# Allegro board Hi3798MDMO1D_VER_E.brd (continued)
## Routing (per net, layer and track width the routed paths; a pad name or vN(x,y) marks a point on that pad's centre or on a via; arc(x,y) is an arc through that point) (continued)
USB0_DM: length 50.8
  TOP w0.127: U1.A6 v2(53.92,47)
  TOP w0.152: v1(81.67,61.35) 81.83,61.51 82.16,61.51 C119.1 D6.1 83.9,61.69 85.3,61.69 86.13,60.87 J12.2
  BOTTOM w0.152: v1(81.67,61.35) 81.39,61.64 81.07,61.64 77.61,65.1 70.71,65.1 69.81,64.21 67.5,64.21 62.77,59.48 55.53,59.48 53.37,57.32 53.37,54.3 53.53,54.15 53.53,53.87 53.37,53.72 53.37,53.44 53.53,53.29 53.53,53.01 53.37,52.86 53.37,52.58 53.53,52.43 53.53,52.15 53.37,51.99 53.37,51.71 53.53,51.56 53.53,51.28 53.37,51.13 53.37,50.85 53.53,50.7 53.53,50.42 53.37,50.27 53.37,49.99 53.53,49.83 53.53,49.55 53.37,49.4 53.37,49.12 53.53,48.97 53.53,48.69 53.37,48.54 53.37,48.26 53.53,48.11 53.53,47.83 53.37,47.68 53.37,46.96 53.53,46.81 53.73,46.81 v2(53.92,47)
USB0_DP: length 50.9
  TOP w0.127: U1.B6 v2(53.92,46.2)
  TOP w0.152: J12.3 86.11,62.85 85.27,62.02 83.79,62.02 D1.1 C113.1 82.22,62.15 81.77,62.15 v1(81.67,62.25)
  BOTTOM w0.152: v2(53.92,46.2) 53.69,46.43 53.37,46.43 53.04,46.76 53.04,57.46 55.4,59.81 62.64,59.81 67.36,64.54 69.68,64.54 70.57,65.43 77.74,65.43 81.21,61.97 81.39,61.97 v1(81.67,62.25)
USB01_1V1: length 0.6
  TOP w0.305: U1.G11 57.52,41.8 v2(57.92,41.4)
USB01_3V3: length 0.6
  TOP w0.305: U1.D7 v2(54.72,44.6)
USB1_DM: length 76.4
  TOP w0.152: v1(36.89,61.77) 37.11,61.77 37.3,61.58 37.3,61.08 37.63,60.75 43.85,60.75 54.87,49.73 54.87,48.59 54.72,48.44 54.54,48.44 54.39,48.28 54.39,47.98 54.54,47.83 54.72,47.83 54.87,47.68 54.87,47.43 54.39,46.94 54.39,45.87 U1.B7 ; U7.7 22.59,30.96 22.26,31.29 20.86,31.29 20.68,31.47 20.68,32.29 20.78,32.39 21.03,32.39 v1(21.24,32.18)
  BOTTOM w0.152: v1(21.24,32.18) 20.1,32.18 19.59,32.69 19.59,33.83 19.08,34.35 J2.4 19.08,36.81 19.91,37.64 19.91,38.3 20.34,38.73 23.52,38.73 25.05,40.26 25.05,53.35 30,58.29 34.95,58.29 37.17,60.51 37.17,61.48 v1(36.89,61.77)
USB1_DP: length 76.4
  TOP w0.152: v1(37.78,61.77) 37.63,61.61 37.63,61.22 37.76,61.08 43.99,61.08 55.2,49.87 55.2,47.29 54.72,46.81 54.72,45.4 U1.C7 ; v1(21.24,32.94) 21.03,32.72 20.65,32.72 20.35,32.43 20.35,31.42 20.23,31.29 19.26,31.29 19.09,31.11 U7.6
  BOTTOM w0.152: v1(21.24,32.94) 20.81,32.51 20.24,32.51 19.92,32.82 19.92,33.52 21.08,34.68 J2.3 21.08,36.81 20.24,37.64 20.24,38.16 20.48,38.4 23.66,38.4 25.38,40.13 25.38,53.21 30.13,57.96 35.09,57.96 37.5,60.37 37.5,61.48 v1(37.78,61.77)
USB3_DM: length 46.2
  TOP w0.152: 63.12,29 63.12,29.12 63.01,29.22 62.75,29.22 62.65,29.12 62.65,28.13 62.8,27.98 63.05,27.98 63.2,27.82 63.2,27.52 63.05,27.37 62.8,27.37 62.65,27.21 62.65,26.91 62.8,26.76 63.05,26.76 63.2,26.6 63.2,26.3 63.05,26.15 62.8,26.15 62.65,25.99 62.65,25.32 65.44,22.53 75.89,22.53 77.26,21.16 77.26,20.07 79.24,18.08 79.24,13.17 83.09,9.32 85.35,9.32 86.41,10.37 86.41,14.04 86.07,14.38 85.59,14.38 85.35,14.13 J13.2
USB3_DP: length 46.1
  TOP w0.152: 63.12,29.8 62.88,29.55 62.62,29.55 62.31,29.25 62.31,25.18 65.3,22.2 75.76,22.2 76.93,21.02 76.93,19.93 78.91,17.95 78.91,13.03 82.96,8.99 85.49,8.99 86.74,10.24 86.74,14.18 86.21,14.71 85.91,14.71 J13.3
USB3_RXN: length 27.9
  TOP w0.152: U1.AB20 65.31,29.21 65.31,25.42 66.15,24.58 77.04,24.58 82.72,18.9 82.72,17.71 83.01,17.42 83.61,17.42 83.85,17.65 J13.5
USB3_RXP: length 27.9
  TOP w0.152: J13.6 83.85,16.86 83.61,17.09 82.87,17.09 82.39,17.57 82.39,18.76 76.9,24.25 66.01,24.25 64.98,25.28 64.98,26.4 64.88,26.51 64.75,26.51 64.6,26.66 64.6,26.96 64.75,27.12 64.88,27.12 64.98,27.22 64.98,28.74 U1.AC20
USB3_TXN: length 26.6
  TOP w0.152: C77.2 80.87,18.43 80.61,18.68 80.61,19.1 76.12,23.59 65.77,23.59 64.17,25.19 64.17,27.53 64.32,27.68 64.4,27.68 64.55,27.83 64.55,28.14 64.4,28.29 64.32,28.29 64.17,28.44 64.17,28.89 63.84,29.22 63.84,29.51 63.97,29.64 64.19,29.64 64.32,29.76 64.32,30.04 64.19,30.17 63.94,30.17 63.84,30.27 63.84,30.52 63.9,30.58 U1.AA19
USB3_TXP: length 26.2
  TOP w0.152: C81.2 80.28,18.63 80.28,18.96 75.98,23.26 65.63,23.26 63.84,25.06 63.84,28.75 63.51,29.08 63.51,30.99 U1.Y19
USB_BOOT: length 9.8
  BOTTOM w0.127: S2.1 78.44,45.18 ; 78.44,45.18 84.64,45.18 S2.2 ; 78.44,45.18 C109.1 R40.1
VDAC_3V3: length 2.6
  TOP w0.305: U1.G19 64,41.88 64,42.52 U1.F19 63.92,42.6 U1.E20 v2(65.12,43.8)
XIN: length 10.8
  TOP w0.203: X2.1 75.61,29.73 75.14,30.2 73.12,30.2 72.33,29.41 C364.1 72.18,29.51 R1.2 70.37,30.17 70.04,30.17 68.01,32.2 67.12,32.2
XOUT: length 7.4
  TOP w0.203: U1.W22 66.71,32.58 68.21,32.58 70.24,30.55 70.6,30.55 R1.1 71.71,30.3 R14.1
$4N774: length 3.5
  TOP w0.381: C43.1 R7.2 67.74,50.39 C71.1 67.34,49.99 67.34,49.53 R21.1
$4N775: length 7.1
  TOP w0.381: R70.1 69.43,53.92 R53.1 C76.1 72.58,53.92 R99.2 73.19,52.89 73.95,52.12 U11.6
$4N782: length 3.5
  TOP w0.381: v1(72.33,52.63) 72.33,52.6 U11.1
  BOTTOM w0.127: v1(72.33,52.63) 73.44,52.63 R73.2 74.01,52.48 74.26,52.73 C8.1
$4N811: length 5.3
  TOP w0.508: R13.2 72.27,11.98 72.27,11.42 71.69,10.84 R101.1 C82.1 ; R13.2 R110.1 ; R13.2 71.88,11.98 71.41,11.98 71.21,12.18 U13.6
$4N812: length 40.1
  TOP w0.127: v1(69.78,45.66) 69.52,45.4 C72.1 68.89,44.75 68.87,44.72 R23.1 ; R102.2 C45.1 72.27,15.53 73.17,16.43 73.17,20.33 v1(74.08,21.23)
  BOTTOM w0.127: v1(69.78,45.66) 70.72,45.66 75.09,41.3 75.09,38.83 78.01,35.91 78.01,25.17 v1(74.08,21.23)
$4N813: length 1
  TOP w0.381: R110.2 R102.1
$4N818: length 3.9
  TOP w0.381: v1(71.72,15.88) 71.7,15.9 71.24,15.9 70.83,15.49 U13.1
  BOTTOM w0.381: R81.2 C5.1 71.54,16.06 v1(71.72,15.88)
$4N881: length 5
  TOP w0.381: U15.5 15.11,40.52 14.77,40.18 R52.1 15.27,39.19 15.38,39.29 R10.1 C84.1
$4N883: length 3.3
  TOP w0.381: R35.2 20.07,38.35 C30.1 R6.2 19.11,39.8 18.94,39.97 U15.1
$4N953: length 3.5
  TOP w0.381: v1(64.5,59.2) 64.96,59.66 U14.5
  BOTTOM w0.381: R105.1 R100.1 64.84,59.53 v1(64.5,59.2)
$4N955: length 4.1
  TOP w0.381: D2.1 73.09,54.89 72.39,55.6 v1(72.39,55.85) U14.1
  BOTTOM w0.381: R95.1 72.54,55.7 v1(72.39,55.85)
$4N956: length 1
  BOTTOM w0.381: R104.1 C83.2
$4N957: length 3.4
  TOP w0.381: v1(64.48,58.17) 64.71,58.39 U14.6
  BOTTOM w0.381: v1(64.48,58.17) 64.86,58.54 C24.1 C83.1
$4N958: length 3.6
  TOP w0.381: v1(64.48,56.39) 64.48,56.9 64.71,57.12 U14.7
  BOTTOM w0.381: v1(64.48,56.39) 64.48,55.75 64.82,55.42 R4.2
$4N975: length 2.9
  TOP w0.381: v1(64.5,54.81) 64.5,55.13 65.22,55.85 U14.8
  BOTTOM w0.381: C44.1 64.91,54.4 v1(64.5,54.81)
$4N980: length 1
  BOTTOM w0.381: C65.1 R95.2
$4N983: length 0.7
  BOTTOM w0.381: C65.2 v1(72.49,58.29)
$4N998: length 1
  TOP w0.381: R70.2 R7.1
$5N541: length 3.7
  TOP w0.381: R144.2 R118.2 75.32,19.63 75.62,19.32 75.62,18.44 Q4.3
$5N549: length 2.1
  TOP w0.381: Q4.1 74.32,15.41 73.82,15.91 R98.2
$6N188: length 2.8
  TOP w0.203: R14.2 C365.1 72.6,32 73.26,31.35 X2.3
$6N1407: length 1.6
  TOP w0.305: U1.E6 53.52,43.4 v2(53.12,43.8)
  BOTTOM w0.381: v2(53.12,43.8) 53.12,43.99 52.76,44.34 R173.1
$6N2001: length 2.5
  TOP w0.127: U1.Y17 v2(62.72,31.8)
  BOTTOM w0.127: R61.2 63,30.49 63.13,30.62 63.13,31.39 63.03,31.49 v2(62.72,31.8)
$6N2177: length 3.1
  TOP w0.203: U1.L19 63.92,38.6 64.32,39 v2(65.12,39)
  BOTTOM w0.305: R85.1 65.62,39.49 v2(65.12,39) 65.52,38.6 R43.1
$6N2315: length 7.6
  TOP w0.127: 51.12,43.4 50.4,44.12 48.83,44.12 47.41,45.54 R5.2
$6N2388: length 2
  TOP w0.127: 67.12,37 68.46,37 68.67,37.21 R65.2
$7N1408: length 1.2
  TOP w0.305: U1.G17 v2(62.72,42.2)
  BOTTOM w0.305: v2(62.72,42.2) 62.59,42.32 C250.2
$7N1630: length 18.6
  TOP w0.127: U1.H21 65.52,40.78 65.92,40.38 65.92,39.84 66.26,39.5 67.66,39.5 69.06,38.1 78.85,38.1 79.26,38.5 v1(79.26,40.77)
  BOTTOM w0.127: R40.2 v1(79.26,40.77)
$7N1639: length 4.1
  TOP w0.305: 55.12,44.2 v2(55.52,44.6)
  BOTTOM w0.305: R87.2 R18.2 55.79,46.63 56.04,46.38 56.04,45.12 v2(55.52,44.6)
$7N1763: length 1.3
  TOP w0.305: U1.F20 v2(65.12,43)
  BOTTOM w0.305: R32.2 65.22,43.1 v2(65.12,43)
$8N1506: length 1.3
  TOP w0.127: U1.W16 v2(61.12,31.8)
  BOTTOM w0.305: v2(61.12,31.8) 61.07,31.85 R45.1
$8N1514: length 4.3
  TOP w0.114: U1.AA7 54.32,30.33 53.88,29.89 53.88,28.63 54.49,28.02 54.89,27.62 54.89,27.24 54.89,27.24 R36.2
$8N1515: length 3.7
  TOP w0.114: U1.AB7 54.15,29.63 54.15,28.74 55.15,27.73 55.15,27.28 55.48,26.94 R37.2
$9N2352: length 1.5
  TOP w0.305: U1.T19 v2(64.32,35)
  BOTTOM w0.381: v2(64.32,35) 64.78,34.54 C255.2
$11N1061: length 4
  TOP w0.127: R54.2 36.94,38.17 36.94,41.62 U3.H8
$11N1180: length 3.9
  TOP w0.127: U6.H8 36.97,27.01 R55.2
$12N1392: length 4.2
  TOP w0.127: R71.2 45.06,13.64 44.98,13.71 41.85,13.71 U21.H8
$12N1506: length 4.5
  TOP w0.127: U20.H8 56.97,13.74 58.61,13.74 59.75,14.88 R75.2
$13N604: length 2.9
  TOP w0.089: U22.K2 89.27,34.12 89.92,34.12
  TOP w0.127: v2(89.95,34.12) 89.92,34.12
  BOTTOM w0.203: 89.95,34.12 90.33,34.5 C124.1 ; 89.95,34.12 89.31,34.75 C123.1 ; 89.95,34.12 v2(89.95,34.12)
$13N728: length 1.9
  TOP w0.254: U19.39 87.51,25.65 87.64,25.53 R68.1
$13N778: length 2
  TOP w0.254: R80.2 87.01,25.4 U19.38
$14N447: length 2
  TOP w0.381: U10.3 82.39,71.5 R15.1
$14N448: length 2.8
  TOP w0.381: U10.4 83.88,70.38 R41.2
$14N488:
  vias: v1(89.88,74.42) v1(89.88,73.53) v1(90.77,74.42) v1(90.77,73.53)
$14N520: length 1.4
  TOP w0.381: U12.3 74.78,12.02 R16.1
$14N521: length 1.3
  TOP w0.381: R42.2 73.72,9.03 U12.4
$14N524:
  vias: v1(79.92,8.3) v1(79.92,7.03) v1(81.19,8.3) v1(81.19,7.03)
$14N708: length 9.3
  TOP w0.152: J13.9 83.85,10.74 83.61,10.97 83,10.97 81.5,12.47 81.5,14.86 80.41,15.95 80.41,16.84 80.08,17.17 C81.1
$14N709: length 9
  TOP w0.152: C77.1 81.01,17.12 80.74,16.85 80.74,16.09 81.83,15 81.83,12.61 83.14,11.3 83.74,11.3 83.85,11.41 J13.8
$15N781: length 19.1
  TOP w0.127: R76.2 26.57,52.76 24.29,55.04 21.45,55.04 v1(20.94,55.55)
  BOTTOM w0.127: v1(20.94,55.55) 20.43,56.05 17.89,56.05 17.49,56.46 17.49,59.48 Q5.1
$15N941: length 2.3
  TOP w0.127: v1(65.41,8.35) 65.41,8.3 65.39,8.33 Q2.1
  BOTTOM w0.127: R31.2 65.95,7.64 65.41,8.17 v1(65.41,8.35)
$15N943: length 2.9
  TOP w0.127: v1(69.28,10.16) 68.41,9.29 Q1.1
  BOTTOM w0.127: R22.2 68.91,10.54 v1(69.28,10.16)
$15N992: length 7.9
  TOP w0.254: LED1.3 67.67,4.34 67.39,4.62 Q1.3 67.39,9.24 R2.2
$15N993: length 10
  TOP w0.254: R34.2 64.23,9.7 63.46,8.93 Q2.3 63.46,5.05 62.59,4.19 LED1.1
$16N996: length 5.3
  TOP w0.356: U5.5 57.71,67.87 57.69,67.88 C363.1
  TOP w0.381: R229.1 R90.2 R66.1 57.08,68.65 56.99,68.56 C363.1
$16N997: length 2.1
  TOP w0.356: C33.2 57.57,66.74 58.04,67.22 U5.6
$16N998: length 2.7
  TOP w0.356: U5.7 v1(60.11,66.57)
  BOTTOM w0.381: v1(60.11,66.57) 60.19,66.49 C32.1
$16N999: length 2.4
  TOP w0.356: U5.8 v1(63.66,66.57)
  BOTTOM w0.381: v1(63.66,66.57) 63.58,66.49 C32.2
$16N1080: length 2
  TOP w0.381: R49.2 R57.1 R91.2
$16N1087: length 1.3
  TOP w0.381: C351.2 58.77,59.42 R193.1
$16N1088: length 8.9
  TOP w0.254: U5.2 60.33,69.82 61.38,68.77 61.38,66.01 C55.1 59.88,64 59.85,63.98 R27.2
$16N1091: length 3.6
  TOP w0.254: R19.1 R27.1 C317.1 R193.2
$16N1106: length 15.8
  TOP w0.254: R74.2 R146.1 59.73,71.67 58.43,71.67 57.82,71.06 57.82,69.41 58.06,69.17 U5.3 58.98,69.15 60.23,69.15 60.74,68.65 60.74,66.16 60.23,65.65 59.85,65.65 59.09,64.89 59.09,64.53 C55.2 58.45,63.9 R19.2
$16N1113: length 1.4
  TOP w0.254: R194.2 62.71,59.04 C350.1
$16N1114: length 3.6
  TOP w0.254: R20.2 R28.2 C316.1 R194.1
$16N1117: length 8.8
  TOP w0.254: U5.13 63.31,69.82 62.01,68.52 62.01,65.78 61.22,64.99 C54.2 61.22,63.9 61.25,63.87 R28.1
$16N1132: length 14.7
  TOP w0.254: R20.1 62.65,63.9 C54.1 62.04,64.79 62.77,65.53 62.77,68.27 63.68,69.17 U5.12 65.59,69.17 65.87,69.45 65.87,70.78 65.52,71.14 64.7,71.14 R145.1 R72.1
$16N1141: length 2
  TOP w0.305: U5.11 65.82,68.52 66.02,68.72 R49.1
$17N163: length 3.3
  TOP w0.508: T2.7 v1(31.43,66.15)
  BOTTOM w0.381: C297.1 30.92,65.64 v1(31.43,66.15) 32.01,65.57 C154.1
$17N165: length 10
  TOP w0.381: J25.9 20.23,76.04 20.23,68.06 R67.1
$17N170: length 15.4
  TOP w0.381: J25.11 33.63,78.01 35.72,78.01 37.09,76.64 R79.1
$17N171: length 12.4
  BOTTOM w0.508: J25.7 30.39,82.65 J25.8 28.56,78.79 R270.2
$17N172: length 2.8
  TOP w0.508: T2.15 25.08,72.55 25.33,72.3 v1(25.61,72.3)
  BOTTOM w0.508: R271.2 25.27,72.64 v1(25.61,72.3)
$17N173: length 2.7
  TOP w0.508: T2.10 v1(31.43,72.15)
  BOTTOM w0.508: R269.2 30.93,72.64 v1(31.43,72.15)
$17N175: length 12.8
  TOP w0.254: J25.6 28.32,80.58 26.91,80.58 26.73,80.4 26.73,79.94 31.1,75.58 31.68,74.99 32.22,74.99 32.7,74.51 T2.9
$17N176: length 11.8
  TOP w0.254: T2.11 30.16,74.64 30.59,75.07 30.59,75.51 26.32,79.78 J25.3
$17N178: length 12
  TOP w0.254: T2.16 23.81,74.64 24.04,74.87 24.7,74.87 24.93,75.09 24.93,75.52 25.41,76 25.41,78.14 23.5,80.05 23.5,81.98 24.29,82.76 J25.1
$17N179: length 11.8
  TOP w0.254: T2.14 26.35,74.61 26.12,74.84 25.54,74.84 25.33,75.04 25.33,75.35 25.82,75.83 25.82,78.31 23.91,80.22 23.91,81.81 24.36,82.26 24.68,82.26 J25.2
$17N180: length 11.4
  BOTTOM w0.508: J25.5 28.36,82.65 J25.4 27.34,74.1 26.78,73.54 R272.2
$17N184: length 3.2
  TOP w0.508: T2.2 v1(25.08,66.15)
  BOTTOM w0.381: C153.1 24.7,65.77 v1(25.08,66.15) 25.66,65.57 C307.1
$17N263: length 6.3
  TOP w0.114: R59.2 27.52,62.25 27.52,62.49 27.42,62.6 25.38,62.6 24.97,63 24.97,63.37 24.85,63.5 24.1,63.5 23.81,63.79 T2.1
$17N268: length 5.1
  TOP w0.114: T2.6 30.16,63.79 30.45,63.5 31.2,63.5 31.32,63.37 31.32,63.1 31.1,62.88 30.21,62.88 29.93,62.6 29.93,62.25 R63.2
$17N269: length 6.2
  TOP w0.114: R62.2 27.79,62.25 27.79,62.6 27.53,62.87 25.49,62.87 25.24,63.12 25.24,63.37 25.37,63.5 26.13,63.5 26.35,63.72 T2.3
$17N270: length 5.1
  TOP w0.114: R64.2 30.2,62.25 30.2,62.49 30.32,62.61 31.21,62.61 31.59,62.99 31.59,63.37 31.72,63.5 32.48,63.5 32.7,63.72 T2.8
$19N506: length 1.3
  TOP w0.127: R268.1 D19.1

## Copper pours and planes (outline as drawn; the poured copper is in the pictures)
1V1_CORE on TOP (solid shape): 72.92,21.62 72.92,19.4 72.81,19.29 68.93,19.29 68.69,19.05 68.69,18.59 68.44,18.33 67.57,18.33 67.19,17.95 65.41,17.95 65.39,17.97 65.39,19.28 66.11,20 66.11,21.66 66.21,21.76 72.78,21.76
1V1_CORE on TOP (solid shape): outline of 81 points within 56.47,32.48 63.99,40.38
1V1_CORE on BOTTOM (solid shape): 68.61,21.15 68.61,18.59 68.49,18.46 66.58,18.46 66.46,18.59 66.46,18.92 67.4,18.92 67.4,19.3 67.02,19.3 67.02,18.92 66.46,18.92 66.46,21.26 66.58,21.38 68.39,21.38
1V1_CORE on BOTTOM (solid shape): 63.61,34.34 63.61,33.73 63.99,33.35 63.99,32.61 63.64,32.25 61.88,32.25 61.67,32.47 61.67,33.07 62.39,33.07 62.39,33.32 62.14,33.32 62.14,33.07 61.67,33.07 61.67,33.64 61.68,33.65 62.52,33.65 62.62,33.75 62.62,34.34 62.67,34.39 63.56,34.39
1V1_CORE on BOTTOM (solid shape): 67.95,30.65 67.95,29.79 68.23,29.51 69.68,29.51 69.78,29.41 69.78,27.53 69.66,27.4 69.17,27.4 69,27.22 68.99,27.15 68.99,26.72 68.87,26.59 68.34,26.59 67.96,26.97 68.49,26.97 68.49,27.35 68.23,27.35 68.23,26.97 67.96,26.97 67.29,27.64 67.27,27.67 67.24,27.72 67.2,27.76 67.15,27.79 67.11,27.81 67.05,27.83 67,27.84 66.95,27.84 66.91,27.84 66.87,27.85 66.71,28.01 66.71,29.4 67.18,29.4 67.19,29.35 67.2,29.3 67.22,29.25 67.24,29.2 67.28,29.16 67.32,29.13 67.36,29.1 67.41,29.08 67.46,29.07 67.51,29.06 67.56,29.06 67.61,29.07 67.66,29.09 67.7,29.11 67.75,29.15 67.78,29.18 67.81,29.22 67.83,29.27 67.85,29.32 67.86,29.37 67.86,29.42 67.85,29.47 67.83,29.52 67.81,29.57 67.78,29.61 67.75,29.65 67.7,29.68 67.66,29.71 67.61,29.72 67.56,29.73 67.51,29.73 67.46,29.73 67.41,29.72 67.36,29.69 67.32,29.67 67.28,29.63 67.24,29.59 67.22,29.55 67.2,29.5 67.19,29.45 67.18,29.4 66.71,29.4 66.71,30.63 66.76,30.68 67.93,30.68
1V1_CORE on BOTTOM (solid shape): outline of 87 points within 56.14,35.71 60.56,40.69
1V1_CORE on POWER03 (solid shape): outline of 1677 points within 56.53,19.48 69.81,41.07
1V1_CPU on TOP (solid shape): 74.99,45.92 74.99,42.76 73.37,41.15 73.37,38.73 72.99,38.35 69.56,38.35 69.35,38.57 69.35,41.61 70.8,43.05 70.8,45.94 70.9,46.05 74.86,46.05
1V1_CPU on TOP (solid shape): 62.32,41.49 62.38,41.5 62.72,41.5 62.95,41.27 62.95,38.1 62.53,37.68 62.48,37.64 62.42,37.56 61.4,37.56 61.3,37.67 61.3,38.83 61.38,38.91 61.63,38.91 61.86,39.14 61.86,39.67 61.68,39.85 61.35,39.85 61.3,39.9 61.3,40.29 61.3,40.31 61.32,40.33 61.46,40.6 61.32,40.87 61.3,40.89 61.3,40.91 61.3,41.07 61.73,41.5 62.26,41.5
1V1_CPU on BOTTOM (solid shape): 63.86,40.79 63.86,40.31 63.62,40.06 63.62,38.72 63.74,38.6 63.74,38 63.63,37.89 62.46,37.89 61.93,37.89 61.71,38.12 61.71,38.23 63.34,38.23 63.34,38.61 62.96,38.61 62.96,38.23 61.71,38.23 61.71,39.12 63.34,39.12 63.34,39.5 62.96,39.5 62.96,39.12 61.71,39.12 61.71,39.5 62.32,39.5 62.32,39.88 61.94,39.88 61.94,39.5 61.71,39.5 61.71,40.13 63.47,40.13 63.47,40.51 63.09,40.51 63.09,40.13 61.71,40.13 61.71,40.64 61.91,40.84 63.81,40.84
1V1_CPU on BOTTOM (solid shape): 73.63,40.35 73.63,37.7 73.35,37.41 69.23,37.41 69.2,37.45 69.2,37.66 68.07,38.79 67.61,38.79 67.47,38.93 67.47,39.04 68.23,39.04 68.23,39.14 68.51,39.14 68.51,39.09 68.51,39.04 68.53,38.98 68.55,38.93 68.58,38.89 68.62,38.85 68.66,38.82 68.71,38.79 68.76,38.77 68.81,38.76 68.87,38.75 68.92,38.76 68.98,38.77 69.03,38.79 69.07,38.82 69.12,38.85 69.15,38.89 69.18,38.93 69.21,38.98 69.22,39.04 69.23,39.09 69.23,39.14 69.22,39.2 69.21,39.25 69.18,39.3 69.15,39.34 69.12,39.38 69.07,39.42 69.03,39.44 68.98,39.46 68.92,39.48 68.87,39.48 68.81,39.48 68.76,39.46 68.71,39.44 68.66,39.42 68.62,39.38 68.58,39.34 68.55,39.3 68.53,39.25 68.51,39.2 68.51,39.14 68.23,39.14 68.23,39.29 67.98,39.29 67.98,39.04 67.47,39.04 67.47,39.52 67.58,39.62 73.25,39.62 73.25,40.01 72.87,40.01 72.87,39.62 67.58,39.62 67.65,39.7 68.54,39.7 69.27,40.43 73.54,40.43
1V1_CPU on POWER03 (solid shape): outline of 325 points within 61.63,38.02 72.84,42.54
1V5_DDR3 on TOP (solid shape): 26.7,46.27 26.7,42.55 27.52,41.73 27.52,39.59 27.21,39.29 24.16,39.29 23.99,39.47 23.99,42.13 23.76,42.36 23.22,42.36 23,42.59 23,45.13 25.71,45.13 25.71,45.08 25.72,45.03 25.73,44.97 25.75,44.92 25.79,44.88 25.82,44.84 25.86,44.81 25.91,44.78 25.96,44.76 26.01,44.75 26.07,44.74 26.12,44.75 26.18,44.76 26.23,44.78 26.27,44.81 26.32,44.84 26.35,44.88 26.38,44.92 26.41,44.97 26.42,45.03 26.43,45.08 26.43,45.13 26.42,45.19 26.41,45.24 26.38,45.29 26.35,45.33 26.32,45.37 26.27,45.41 26.23,45.43 26.18,45.45 26.12,45.46 26.07,45.47 26.01,45.46 25.96,45.45 25.91,45.43 25.86,45.41 25.82,45.37 25.79,45.33 25.75,45.29 25.73,45.24 25.72,45.19 25.71,45.13 23,45.13 23,46.33 23.2,46.53 26.45,46.53
1V5_DDR3 on TOP (solid shape): outline of 88 points within 51.67,30.75 60.13,40.41
1V5_DDR3 on BOTTOM (solid shape): 44.59,38.2 44.59,36.9 44.46,36.77 43.16,36.77 42.96,36.98 42.96,38.12 43.16,38.32 44.46,38.32
1V5_DDR3 on BOTTOM (solid shape): 47.37,18.91 47.37,17.52 47.19,17.34 46.16,17.34 45.96,17.55 45.96,18.89 46.11,19.05 47.23,19.05
1V5_DDR3 on BOTTOM (solid shape): 49.31,55.42 49.31,49.2 49.06,48.94 46.64,48.94 46.52,49.07 46.52,49.45 47.28,49.45 47.28,49.83 46.9,49.83 46.9,49.45 46.52,49.45 46.52,50.21 46.77,50.47 46.77,51.99 47.53,51.99 47.53,52.37 47.15,52.37 47.15,51.99 46.77,51.99 46.77,55.55 46.9,55.67 49.06,55.67
1V5_DDR3 on BOTTOM (solid shape): 56.52,34.36 56.52,33.6 56.63,33.5 58.45,33.5 58.61,33.65 60.28,33.65 60.41,33.52 60.41,32.99 60.38,32.96 55.3,32.96 55.25,33.02 55.25,33.07 59.98,33.07 59.98,33.32 59.72,33.32 59.72,33.07 58.58,33.07 58.58,33.32 58.33,33.32 58.33,33.07 55.25,33.07 55.25,33.45 56.04,33.45 56.04,33.7 55.66,33.7 55.66,33.45 55.25,33.45 55.25,33.83 56.04,33.83 56.04,34.08 55.66,34.08 55.66,33.83 55.25,33.83 55.25,34.36 55.33,34.44 56.45,34.44
1V5_DDR3 on BOTTOM (solid shape): outline of 99 points within 51.39,29.94 54.26,40.33
1V5_DDR3 on POWER03 (solid shape): outline of 11002 points within 24.6,4.59 65.12,54.2
3V3 on TOP (solid shape): 71.54,8.56 71.54,6.65 71.41,6.52 69.88,6.52 69.76,6.65 69.76,6.86 71.09,6.86 71.09,7.24 70.2,7.24 70.2,6.86 69.76,6.86 69.76,8.55 69.98,8.77 71.32,8.77
3V3 on TOP (solid shape): 76.42,51.18 76.42,49.46 76.29,49.33 74.98,49.33 74.98,49.34 73.31,49.34 73.22,49.42 73.22,50.25 73.31,50.34 74.84,50.34 74.86,50.36 75.02,50.53 75.02,51.31 75.15,51.44 76.17,51.44
3V3 on TOP (solid shape): 77.26,64.19 77.26,62.57 77.18,62.48 73.25,62.48 72.75,61.99 72.75,60.57 72.42,60.24 71.55,60.24 71.47,60.33 71.47,61.7 71.32,61.85 71.32,64.11 71.6,64.39 77.06,64.39
3V3 on TOP (solid shape): 17.38,46.63 17.38,44.45 17.15,44.22 17.15,42.11 17.1,42.06 15.02,42.06 14.92,42.16 14.92,43.05 16.86,43.05 16.86,43.43 16.35,43.43 16.35,43.05 14.92,43.05 14.92,43.69 16.86,43.69 16.86,44.07 16.35,44.07 16.35,43.69 14.92,43.69 14.92,46.58 15.1,46.76 17.26,46.76
3V3 on TOP (solid shape): 68.06,12.95 69.15,12.95 69.25,12.85 69.25,11.22 68.39,10.36 68.37,10.36 68.27,10.26 67.3,10.26 67.28,10.29 67.25,10.33 67.21,10.37 67.17,10.4 67.12,10.43 67.07,10.45 67.02,10.46 66.96,10.46 66.91,10.46 66.86,10.45 66.8,10.43 66.76,10.4 66.71,10.37 66.67,10.33 66.64,10.29 66.63,10.26 65.73,10.26 65.73,10.54 67.79,10.54 67.79,11.05 67.28,11.05 67.28,10.54 66.64,10.54 66.64,11.05 66.13,11.05 66.13,10.54 65.73,10.54 65.73,10.77 65.31,11.19 65.31,12.19 67.66,12.19 67.66,12.7 67.15,12.7 67.15,12.19 65.31,12.19 65.31,12.92 65.44,13.05 67.95,13.05
3V3 on BOTTOM (solid shape): 17.36,46.53 17.36,44.37 17.2,44.22 14.99,44.22 14.87,44.34 14.87,46.53 15.02,46.68 17.2,46.68
3V3 on BOTTOM (solid shape): 73.06,9.19 73.06,7.29 72.93,7.16 69.38,7.16 69.25,7.29 69.25,8.29 70.28,9.32 72.93,9.32
3V3 on BOTTOM (solid shape): 66.7,32.87 66.71,32.85 66.71,31.29 66.43,31.01 65.24,31.01 64.85,31.39 64.85,31.75 65.63,31.75 65.63,32.13 65.25,32.13 65.25,31.75 64.85,31.75 64.85,32.79 64.98,32.91 66.66,32.91
3V3 on BOTTOM (solid shape): 68.62,11.76 68.62,11.1 68.52,10.99 68.21,10.99 68.18,10.97 68.16,10.97 68.1,10.97 68.08,10.97 68.06,10.99 67.19,10.99 67.16,10.97 67.14,10.97 65.86,10.97 65.68,11.15 65.68,12.95 65.85,13.13 67.25,13.13
3V3 on BOTTOM (solid shape): 79.18,58.39 82.85,58.39 82.86,58.38 83,58.38 84.44,56.94 86.16,56.94 86.38,56.73 86.38,54.22 86.18,54.02 84.3,54.02 82.69,55.63 80.36,55.63 80.1,55.37 80.1,52.2 79.85,51.94 77.69,51.94 76.78,51.03 76.78,49.81 76.25,49.28 75.15,49.28 74.9,49.53 74.9,51.44 75.02,51.56 75.41,51.56 77.56,53.71 77.56,54.89 77.59,54.96 77.67,54.99 78.07,55.45 77.52,55.71 77.48,55.69 73.62,59.56 71.47,59.56 71.18,59.85 71.18,61.25 71.32,61.39 71.32,63.99 71.52,64.19 73.38,64.19
3V3 on POWER03 (solid shape): outline of 7664 points within 11.89,1.91 90.84,59.41
3V3_MOS on TOP (solid shape): 78.33,45.59 78.33,43.18 78.07,42.93 75.66,42.93 75.41,43.18 75.41,45.72 75.53,45.85 78.07,45.85
3V3_MOS on TOP (solid shape): 53.37,43.07 54.31,43.07 55.38,42.01 55.38,41.7 55.28,41.6 54.42,41.6 53.89,42.12 53.44,42.12 53.15,42.41 52.64,42.41 52.54,42.52 52.54,42.74 52.99,43.2 53.25,43.2
3V3_MOS on TOP (solid shape): 58.97,43.9 58.97,43.11 58.84,42.97 56.83,42.97 56.65,42.79 56.4,42.79 56.27,42.92 56.27,43.18 56.5,43.4 56.5,44.27 56.65,44.42 58.45,44.42
3V3_MOS on TOP (solid shape): 63.76,43.1 63.76,42.92 63.56,42.72 63.56,42.45 63.75,42.26 63.75,42.05 63.74,42.04 63.65,41.93 63.62,41.8 63.69,41.59 63.89,41.49 63.91,41.49 64.02,41.49 64.14,41.37 64.14,40.13 63.63,39.61 63.63,39.49 63.63,39.49 63.62,39.39 63.63,39.3 63.64,39.29 63.64,38.71 63.63,38.7 63.62,38.58 63.65,38.46 63.65,38.45 63.65,38.36 64.54,37.47 64.54,37.3 64.04,36.8 63.66,36.8 63.1,37.36 63.1,41.37 62.96,41.51 62.96,41.94 63.05,42.06 63.08,42.21 63.08,42.36 62.9,42.54 62.87,42.54 62.87,43.48 63,43.61 63.25,43.61
3V3_MOS on BOTTOM (solid shape): 18.38,53.89 18.38,52.88 18.25,52.75 16.98,52.75 16.85,52.88 16.85,53.89 16.98,54.02 18.25,54.02
3V3_MOS on BOTTOM (solid shape): 24.55,27.1 24.55,25.45 24.42,25.32 21.75,25.32 21.62,25.45 21.62,27.1 21.75,27.22 24.42,27.22
3V3_MOS on BOTTOM (solid shape): 74.2,11.48 74.2,9.7 74.08,9.57 72.32,9.57 72.17,9.72 72.17,11.29 72.48,11.6 74.08,11.6
3V3_MOS on BOTTOM (solid shape): 55.48,42.01 55.48,40.25 55.47,40.24 54.63,40.24 54.62,40.25 54.62,41.44 54.31,41.74 54.31,42.01 54.4,42.1 55.39,42.1
3V3_MOS on BOTTOM (solid shape): 66.46,37.59 66.46,36.8 66.4,36.75 65.62,36.75 65.39,36.98 64.22,36.98 64.07,37.13 65.44,37.13 65.44,37.38 65.19,37.38 65.19,37.13 64.07,37.13 64.07,37.61 66.43,37.61
3V3_MOS on BOTTOM (solid shape): 22.19,60.75 22.19,56.94 22.06,56.82 19.9,56.82 19.77,56.94 19.77,57.15 21.81,57.15 21.81,57.53 21.43,57.53 21.43,57.15 19.77,57.15 19.77,58.8 20.41,58.8 20.41,59.18 20.03,59.18 20.03,58.8 19.77,58.8 19.77,60.75 19.9,60.88 22.06,60.88
3V3_MOS on BOTTOM (solid shape): 51.82,44.39 51.82,43.56 51.95,43.43 53.22,43.43 53.35,43.3 53.35,42.79 53.3,42.74 52.87,42.74 52.64,42.97 51.22,42.97 51.14,43.05 51.14,43.43 51.66,43.43 51.66,44.07 51.4,44.07 51.4,43.43 51.14,43.43 51.14,44.45 51.19,44.5 51.72,44.5
3V3_MOS on BOTTOM (solid shape): 56.75,43.84 56.75,42.95 56.55,42.74 55.3,42.74 55.28,42.77 55.28,42.85 55.91,42.85 55.91,43.1 55.66,43.1 55.66,42.85 55.28,42.85 55.28,43.23 56.55,43.23 56.55,43.48 56.3,43.48 56.3,43.23 55.28,43.23 55.28,43.3 55.33,43.35 55.79,43.35 55.99,43.56 55.99,43.81 56.07,43.89 56.7,43.89
3V3_MOS on BOTTOM (solid shape): 57.69,45.21 57.69,44.98 57.92,44.75 58.48,44.75 58.58,44.65 58.58,44.19 58.72,44.05 58.8,44.05 58.96,43.89 58.96,43.1 58.84,42.97 57.97,42.97 57.82,43.12 57.82,43.18 58.39,43.18 58.39,43.43 58.13,43.43 58.13,43.18 57.82,43.18 57.82,43.89 57.59,44.12 58.33,44.12 58.33,44.37 58.07,44.37 58.07,44.12 57.59,44.12 57.01,44.7 57.01,45.21 57.06,45.26 57.64,45.26
3V3_MOS on BOTTOM (solid shape): 63.92,43.79 63.92,43.58 64.07,43.43 64.6,43.43 64.75,43.28 64.75,42.83 64.97,42.62 66.99,42.62 67.37,43 67.37,43.28 67.5,43.4 69.66,43.4 69.71,43.35 69.71,42.57 69.63,42.49 68.18,42.49 67.31,41.62 65.41,41.62 65.12,41.91 63.45,41.91 63.1,42.26 63.1,43.23 63.66,43.23 63.66,43.48 63.41,43.48 63.41,43.23 63.1,43.23 63.1,43.76 63.18,43.84 63.28,43.84 63.31,43.86 63.84,43.86
3V3_MOS on POWER03 (solid shape): outline of 7622 points within 16.8,9.7 77.81,72.44
3V3_MOS_FLASH on TOP (solid shape): 79.98,52.32 79.98,50.16 78.43,48.61 78.43,47.22 78.33,47.12 75.41,47.12 75.28,47.24 75.28,48.77 75.41,48.9 76.55,48.9 76.68,49.02 76.68,52.32 76.8,52.45 79.85,52.45
3V3_MOS_FLASH on BOTTOM (solid shape): outline of 346 points within 76.93,23.37 91.6,51.69
3V3_SD on TOP (solid shape): 13.7,56.21 13.7,55.19 13.55,55.04 11.34,55.04 11.26,55.11 11.26,55.8 11.34,55.88 12.76,55.88 12.89,56 12.89,56.21 13.04,56.36 13.55,56.36
3V3_SD on BOTTOM (solid shape): 17.74,55.93 17.75,55.93 17.81,55.86 20.35,55.86 20.41,55.8 20.41,52.88 20.28,52.75 18.88,52.75 18.76,52.88 18.76,54.15 18.63,54.28 16.47,54.28 15.71,55.04 13.04,55.04 12.92,55.16 12.92,56.31 13.04,56.43 17.23,56.43
3V3_WIFI on TOP (solid shape): 26.32,30.78 26.32,28.75 26.2,28.62 25.82,28.62 24.26,27.07 24.23,27.07 24.12,27.08 24.02,27.05 23.91,26.98 23.84,26.87 23.82,26.84 23.62,26.84 23.6,26.87 23.28,27.08 22.95,26.87 22.93,26.84 17.05,26.84 16.93,26.97 16.93,27.73 17.43,28.24 23.28,28.24 24.04,29 24.04,30.78 24.29,31.03 26.07,31.03
3V3_WIFI on BOTTOM (solid shape): 17.81,37 17.81,33.7 18.58,32.94 18.58,27.99 19.08,27.48 20.74,27.48 21.12,27.1 21.12,25.45 20.99,25.32 20.23,25.32 19.47,26.08 16.8,26.08 16.29,26.59 16.29,37 16.54,37.26 17.56,37.26
5V0 on TOP (solid shape): 85.44,80.87 85.44,77.09 84.61,76.26 81.31,76.26 80.68,75.63 80.68,56.52 80.43,56.26 75.91,56.26 75.44,56.74 74.72,56.74 74.54,56.57 73.55,56.57 73.34,56.77 70.2,56.77 70.07,56.9 70.07,57.15 75.53,57.15 75.53,57.53 75.15,57.53 75.15,57.15 74.9,57.15 74.9,57.53 74.52,57.53 74.52,57.15 70.07,57.15 70.07,57.4 70.2,57.53 72.99,57.53 73.63,58.17 77.3,58.17 77.69,58.56 77.69,64.33 76.62,65.41 76.62,65.71 77.38,65.71 77.38,66.09 77,66.09 77,65.71 76.62,65.71 76.62,66.34 77.38,66.34 77.38,66.72 77,66.72 77,66.34 76.62,66.34 76.62,74.85 80.55,78.79 80.55,79.49 82.31,81.25 85.06,81.25
5V0 on BOTTOM (solid shape): 74.21,16.67 74.21,16.67 74.28,16.6 74.78,16.6 74.87,16.51 75.33,16.51 75.84,16 75.84,14.36 75.5,14.02 74.99,14.02 74.91,13.94 74.91,13.15 74.76,13 73.69,13 73.57,13.13 73.57,16.68 73.69,16.81 74.06,16.81
5V0 on BOTTOM (solid shape): 85.63,80.5 85.63,77 85.38,76.74 81.67,76.74 79.92,75 79.92,69.03 79.69,68.8 77.63,68.8 77.38,69.06 77.38,75.91 81.25,79.78 81.25,80.47 82.33,81.55 84.59,81.55
5V0 on POWER03 (solid shape): outline of 811 points within 73.57,13.25 83.85,61.42
5V0_MOS on TOP (solid shape): 84.3,74.4 83.53,73.63 81.02,73.63 80.98,73.67 80.98,75.3 81.55,75.87 84.3,75.87
5V0_MOS on TOP (solid shape): 69.4,66.28 69.4,65.14 68.77,64.51 67.88,64.51 67.75,64.63 67.75,65.52 67.88,65.65 68.64,65.65 68.89,65.9 68.89,66.28 69.02,66.41 69.27,66.41
5V0_MOS on TOP (solid shape): 78.29,14.28 78.29,10.69 78.19,10.59 76.49,10.59 76.34,10.74 76.34,13.86 76.46,13.99 76.49,14 76.5,14 76.83,14.1 76.94,14.44 76.94,14.46 76.95,14.48 77,14.52 78.04,14.52
5V0_MOS on BOTTOM (solid shape): 79.79,17.83 79.79,12.75 79.41,12.37 77.63,12.37 77.43,12.57 77.43,13.97 77.78,14.33 78.2,14.33 78.48,14.61 78.48,16.87 78.28,17.07 75.9,17.07 75.89,17.06 74.58,17.06 74.33,17.32 74.33,19.1 74.58,19.35 78.27,19.35
5V0_MOS on BOTTOM (solid shape): 47.28,62.4 47.28,61.51 47.02,61.26 45.25,61.26 45.12,61.13 45.12,59.1 44.99,58.97 44.36,58.97 44.23,59.1 44.23,61.13 44.1,61.26 43.47,61.26 43.34,61.39 43.34,61.77 44.23,61.77 44.23,62.15 43.85,62.15 43.85,61.77 43.34,61.77 43.34,62.4 43.47,62.53 47.15,62.53
5V0_MOS on POWER03 (solid shape): outline of 4142 points within 42.45,16.96 83.41,77.39
AVDD11_PLL012 on BOTTOM (solid shape): 62.26,37.46 62.26,36.9 62.39,36.77 63.1,36.77 63.13,36.75 63.13,35.96 63.23,35.86 63.48,35.86 63.51,35.83 63.51,35.15 63.48,35.12 62.67,35.12 62.65,35.15 62.65,36.11 62.9,36.11 62.9,36.37 62.77,36.37 62.77,36.11 62.65,36.11 62.65,36.17 62.44,36.37 61.78,36.37 61.71,36.44 61.71,36.75 62.14,36.75 62.14,37 61.88,37 61.88,36.75 61.71,36.75 61.71,37.46 61.73,37.49 62.24,37.49
AVDD11_USB3 on TOP (solid shape): 62.52,35.53 62.52,34.49 62.44,34.41 62.19,34.41 61.32,35.28 61.32,35.53 61.4,35.61 62.44,35.61
AVDD11_USB3 on BOTTOM (solid shape): 62.14,35.33 62.14,34.82 62.09,34.77 61.73,34.77 61.63,34.67 61.63,34.51 61.71,34.44 62.21,34.44 62.21,33.96 61.6,33.96 61.55,34.01 60.51,34.01 60.08,34.44 60.08,35.1 60.74,35.1 60.74,35.35 60.49,35.35 60.49,35.1 60.08,35.1 60.08,35.73 60.11,35.76 61.71,35.76
AVDD33_ADAC on BOTTOM (solid shape): 64.04,45.87 64.04,45.06 64.13,44.97 64.72,44.97 64.75,44.93 64.75,43.73 64.58,43.56 64.17,43.56 64.04,43.68 64.04,44.01 63.92,44.14 63.38,44.14 63.37,44.15 63.19,44.15 63.15,44.2 64.48,44.2 64.48,44.58 64.1,44.58 64.1,44.2 63.15,44.2 63.1,44.24 63.1,44.45 63.85,44.45 63.85,44.83 63.47,44.83 63.47,44.45 63.1,44.45 63.1,44.88 62.92,45.06 62.92,45.87 62.98,45.92 63.99,45.92
AVDD33_PLL01 on BOTTOM (solid shape): 68.11,37.38 68.11,35.94 67.9,35.73 67.9,35.45 67.42,34.97 65.74,34.97 65.49,35.23 65.95,35.23 65.95,35.48 67.47,35.48 67.47,35.73 67.22,35.73 67.22,35.48 65.69,35.48 65.69,35.23 65.49,35.23 65.26,35.45 64.12,35.45 64.04,35.53 64.04,35.89 64.19,36.04 64.8,36.04 64.82,36.03 65.5,36.03 65.92,35.61 66.73,35.61 67.12,35.99 67.12,37.54 67.19,37.61 67.88,37.61
AVDD33_USB2 on BOTTOM (solid shape): 67.42,41.02 67.42,40.25 67.34,40.18 65.62,40.18 65.01,39.57 64.22,39.57 64.09,39.7 64.09,39.9 64.25,40.05 64.37,40.05 64.96,40.63 64.96,40.64 65.3,40.98 66.39,40.98 66.48,41.07 67.37,41.07
GND on TOP (solid shape): 69.74,59.94 69.74,55.7 69.59,55.55 67.23,55.55 67.13,55.65 67.13,59.89 67.33,60.1 69.59,60.1
GND on TOP (solid shape): 78.77,42.09 78.77,38.81 78.39,38.43 75.55,38.43 74.9,39.08 74.9,41.6 75.66,42.36 78.51,42.36
GND on TOP (solid shape): 73.05,52.1 73.05,49.75 72.93,49.63 72.6,49.63 72.55,49.68 72.55,50.52 72.5,50.57 70.24,50.57 69.93,50.87 69.93,51.35 69.99,51.41 70.39,51.41 70.62,51.18 72.47,51.18 72.53,51.23 72.53,52.09 72.68,52.24 72.91,52.24
GND on TOP (solid shape): 68.69,68.29 68.69,66.08 68.51,65.9 67.62,65.9 67.5,66.03 67.5,67.05 67.36,67.18 68.04,67.18 68.04,67.56 67.66,67.56 67.66,67.18 67.36,67.18 67.24,67.3 67.24,68.14 67.29,68.19 67.8,68.19 68.08,68.47 68.51,68.47
GND on TOP (solid shape): 55.99,68.09 55.99,67.48 56.52,66.95 56.52,66.08 56.78,65.83 57.39,65.83 57.57,65.65 57.57,61.33 58,60.9 58.5,60.9 58.53,60.89 58.55,60.88 58.56,60.85 58.56,60.09 58.02,59.56 58.02,58.34 57.87,58.18 57.69,58.18 54.57,61.31 54.57,66.21 56.17,66.21 56.17,66.59 55.79,66.59 55.79,66.21 54.57,66.21 54.57,67.96 54.72,68.12 55.96,68.12
GND on TOP (solid shape): 19.66,46.56 19.66,44.62 19.53,44.49 18.51,44.49 18,43.98 18,42 18.13,41.87 22.13,41.87 22.36,42.1 23.28,42.1 23.44,41.94 23.44,38.95 23.3,38.81 20.67,38.81 20.59,38.88 20.59,39.42 21.37,39.42 21.37,39.8 20.99,39.8 20.99,39.42 20.59,39.42 20.59,40.36 19.86,41.09 18.19,41.09 18.05,40.95 18.05,40.03 17.95,39.93 17.55,39.93 17.43,40.05 17.43,40.95 17.3,41.08 15.95,41.08 15.87,41.16 15.87,41.73 15.94,41.8 17.18,41.8 17.46,42.08 17.46,44.1 17.96,44.59 17.96,46.59 18.11,46.74 19.48,46.74
GND on TOP (solid shape): 66.2,38.27 68.22,38.27 68.45,38.05 68.45,37.79 68.17,37.51 67.75,37.51 67.6,37.66 65.92,37.66 65.83,37.77 65.83,37.79 65.51,38.1 65.22,37.77 65.19,37.7 65.12,37.66 64.55,37.66 64.09,38.12 64.09,38.32 64.11,38.36 64.17,38.43 64.21,38.51 64.22,38.52 64.49,38.79 64.84,38.79 64.86,38.79 64.87,38.78 65.13,38.66 65.38,38.79 65.39,38.8 65.41,38.81 65.67,38.81
GND on TOP (solid shape): 86.32,18.08 86.41,18.05 87.58,16.88 87.58,11.3 88.99,9.89 88.99,8.32 85.78,8.49 87.82,6.01 87.25,5.44 84.56,5.44 84.29,5.72 84.29,7.97 85.1,8.78 85.55,8.78 85.57,8.78 86.94,10.15 86.94,14.49 86.65,14.79 86.65,16.18 85.89,16.94 85.89,17.01 85.91,17.03 85.98,17.09 86.04,17.15 86.25,17.56 86.24,18.01
GND on TOP (solid shape): 55.03,19.56 55.03,19.32 55.36,18.99 55.36,18.06 55.35,18.03 55.32,18.01 55.08,17.66 55.37,17.36 55.39,17.35 55.51,17.23 55.52,17.22 56.01,17.05 55.94,17.57 55.92,17.58 55.91,17.61 55.91,17.75 56.12,17.95 56.12,18.09 56.12,18.33 56.47,18.69 56.47,19.12 56.57,19.22 56.68,19.22 56.78,19.12 56.78,18.72 56.42,18.36 56.42,18.34 56.41,18.31 56.44,17.84 56.89,17.96 56.89,17.97 57.27,18.35 58.19,18.35 58.28,18.26 58.28,18.08 58.08,17.88 57.2,17.88 57.19,17.88 57.13,17.88 56.83,17.57 56.83,17.51 56.82,17.5 56.82,17.2 56.68,17.07 56.25,17.07 55.97,16.78 55.94,16.77 55.92,16.78 55.78,16.79 55.64,16.74 55.63,16.73 54.86,16.73 54.84,16.75 54.83,16.76 54.72,16.91 54.54,16.98 54.52,16.98 54.26,17.24 54.26,19.63 54.42,19.78 54.81,19.78
GND on TOP (solid shape): 51.75,39.92 51.75,39.67 51.38,39.31 51.38,39.3 51.2,39.09 51.23,38.82 51.28,38.76 51.35,38.69 51.39,38.69 51.52,38.66 51.65,38.69 51.66,38.69 51.75,38.69 51.86,38.81 52,38.81 52.15,38.65 52.15,38.51 52.14,38.48 52.13,38.48 52.04,38.38 51.99,38.25 51.99,38.23 51.88,38.12 51.86,38.1 51.84,38.09 51.76,38.06 51.67,37.99 51.37,37.99 51.34,38.01 51.19,38.1 50.99,38.08 50.96,38.1 50.62,38.44 50.61,38.46 50.61,38.49 50.52,38.83 50.17,38.86 50.16,38.86 50.1,38.86 49.79,39.16 48.83,39.16 48.75,39.24 48.75,39.52 48.85,39.62 49.4,39.62 49.41,39.61 49.84,39.61 50,39.45 50.01,39.43 50.02,39.41 50.3,39.09 50.62,39.37 50.66,39.43 50.72,39.46 50.96,39.56 51.06,39.79 51.08,39.86 51.15,39.89 51.27,39.93 51.39,40.03 51.41,40.04 51.63,40.04
GND on TOP (solid shape): 67.29,46.71 67.29,45.62 67.04,45.36 67.04,43.73 67.03,43.7 67.01,43.68 66.84,43.52 66.83,43.3 66.84,43.29 66.84,42.9 65.91,41.97 65.84,41.95 65.76,41.98 65.28,41.99 65.39,41.52 65.45,41.45 65.42,41.36 65.24,41.17 65.24,41.11 65.23,41.1 65.22,41 65.23,40.9 65.24,40.89 65.24,40.33 64.91,40 64.6,40 64.35,40.25 64.35,41.78 65.26,42.69 65.27,42.69 65.46,43 65.27,43.3 65.24,43.33 65.21,43.42 65.26,43.49 65.36,44.04 64.82,43.94 64.74,43.88 64.65,43.91 64.63,43.94 64.43,44.12 64.16,44.1 64.14,44.09 64.08,44.04 64.02,43.96 63.71,43.96 63.66,44.01 63.66,44.32 64.08,44.74 64.14,44.78 64.18,44.84 64.55,45.21 64.55,45.87 64.65,45.97 65.77,45.97 66.03,45.71 66.03,45.7 66.35,45.49 66.62,45.76 66.63,45.78 66.95,46.1 66.95,46.77 66.96,46.78 67.22,46.78
GND on TOP (solid shape): outline of 85 points within 84.87,35.18 87.77,38.09
GND on TOP (solid shape): outline of 303 points within 48.73,27.12 52.46,33.04
GND on TOP (solid shape): outline of 440 points within 33.05,16.94 41.99,30.13
GND on TOP (solid shape): outline of 690 points within 32.9,31.95 47.1,45.61
GND on TOP (solid shape): outline of 873 points within 38.18,9.42 52,24.07
GND on TOP (solid shape): outline of 2306 points within 37.35,26.97 77.05,51.53
GND on TOP (solid shape): outline of 4460 points within 10.64,0.51 96.12,87.84
GND on BOTTOM (solid shape): 17.27,58.39 17.27,56.98 17.23,56.94 13.04,56.94 12.92,57.07 12.92,57.65 13.09,57.83 14.67,57.83 15.39,58.56 17.11,58.56
GND on BOTTOM (solid shape): 51.75,32.71 51.75,32.53 50.91,31.69 50.91,30.04 50.83,29.97 49.87,29.97 49.79,30.04 49.79,32 50.61,32.81 51.65,32.81
GND on BOTTOM (solid shape): 42.55,43.96 42.55,43.58 42.4,43.43 42.07,43.43 41.93,43.57 41.3,43.57 41.23,43.63 41.23,43.94 41.88,43.94 41.88,44.32 41.5,44.32 41.5,43.94 41.23,43.94 41.23,44.24 40.28,45.19 40.28,45.5 40.5,45.72 40.8,45.72
GND on BOTTOM (solid shape): 67.76,17.92 68.36,17.92 68.45,17.83 68.45,16.09 68.46,16.09 70.96,13.59 70.96,12.7 70.58,12.32 69.02,12.32 67.84,13.51 67.84,15.19 66.67,16.36 66.67,17.4 67.4,17.4 67.4,17.78 67.02,17.78 67.02,17.4 66.67,17.4 66.67,18.15 67.52,18.15
GND on BOTTOM (solid shape): 51.72,21.26 51.72,19.65 51.63,19.55 51.63,19 51.47,18.84 50.33,18.84 50.2,18.97 50.2,20.32 51.4,20.32 51.4,20.7 51.02,20.7 51.02,20.32 50.2,20.32 50.2,20.95 51.4,20.95 51.4,21.34 51.02,21.34 51.02,20.95 50.2,20.95 50.2,21.51 49.92,21.79 48.68,21.79 48.32,21.43 48.32,19.76 48.12,19.55 45.2,19.55 44.88,19.87 44.88,20.53 48.27,23.92 49.06,23.92
GND on BOTTOM (solid shape): 41.28,40.86 41.28,40.71 41.44,40.56 41.44,39.87 41.69,39.62 45.47,39.62 47,38.1 47,37.69 43.98,34.67 43.98,32.71 43.6,32.33 42.4,32.33 42.17,32.56 42.17,33.48 42.27,33.57 43.34,33.57 43.47,33.7 43.47,35.61 43.34,35.73 41.44,35.73 41.31,35.86 41.31,36.24 42.07,36.24 42.07,36.5 41.69,36.5 41.69,36.24 41.31,36.24 41.31,36.47 41.16,36.62 40.95,36.62 40.8,36.77 40.8,38.3 42.73,38.3 42.73,36.8 42.99,36.55 44.71,36.55 44.84,36.67 44.84,38.32 44.69,38.48 42.91,38.48 42.73,38.3 40.8,38.3 40.8,38.86 42.77,38.86 42.77,39.24 42.39,39.24 42.39,38.86 40.8,38.86 40.8,39.62 41.24,39.62 41.24,40.01 40.99,40.01 40.99,39.62 40.8,39.62 40.8,40.91 40.85,40.97 41.18,40.97
GND on BOTTOM (solid shape): 45.7,28.34 45.7,27.25 43.86,25.41 43.86,24.98 42.4,23.52 41.13,23.52 37.72,20.11 37.71,20.1 37.69,20.08 37.66,20.08 37.63,20.08 37.6,20.09 37.58,20.11 37.56,20.14 37.55,20.16 37.55,20.18 37.55,20.44 41.39,24.28 41.39,25.02 42,25.02 42,25.4 41.62,25.4 41.62,25.02 41.39,25.02 41.39,26.17 42.18,26.17 42.18,26.12 42.19,26.07 42.21,26.02 42.24,25.98 42.27,25.94 42.3,25.9 42.35,25.87 42.39,25.85 42.43,25.84 42.53,25.74 42.53,25.06 43.29,25.06 43.29,25.83 43.22,25.84 43.21,25.85 43.2,25.89 42.84,26.25 42.83,26.29 42.81,26.33 42.78,26.37 42.74,26.41 42.7,26.44 42.66,26.47 42.61,26.49 42.56,26.5 42.51,26.5 42.46,26.49 42.41,26.48 42.36,26.46 42.32,26.43 42.28,26.4 42.25,26.36 42.22,26.32 42.2,26.27 42.18,26.22 42.18,26.17 41.39,26.17 41.39,26.87 40.95,27.3 42.13,27.3 42.13,27.69 41.75,27.69 41.75,27.3 40.95,27.3 40.6,27.66 40.6,27.96 40.83,28.19 42.2,28.19 42.68,28.67 45.37,28.67
GND on BOTTOM (solid shape): outline of 127 points within 41.56,41.19 52.56,52.8
GND on BOTTOM (solid shape): outline of 342 points within 21.88,3.24 74.27,43
GND on BOTTOM (solid shape): outline of 7998 points within 10.64,0.51 96.12,87.84
GND on GND02 (solid shape): outline of 27993 points within 10.64,0.51 96.12,87.84
GND on POWER03 (solid shape): outline of 2109 points within 36.58,16.8 56.23,48.2
GND on POWER03 (solid shape): outline of 4329 points within 10.64,0.51 96.12,87.84
VDD_AUDIO on TOP (solid shape): 66.98,68.04 66.98,67.17 67.23,66.92 67.23,64.63 67.1,64.51 65.96,64.51 65.83,64.63 65.83,67.18 66.64,67.18 66.64,67.56 66.26,67.56 66.26,67.18 65.83,67.18 65.83,68.02 65.95,68.14 66.87,68.14
DDR_VTT on TOP (solid shape): 41.27,52.28 41.27,51.44 41.08,51.25 38.26,51.25 38.16,51.35 37.98,51.35 37.95,51.37 37.93,51.41 37.93,51.76 37.89,51.78 37.88,51.81 37.88,52.12 37.63,52.12 37.63,51.81 37.61,51.78 37.58,51.76 36.91,51.76 36.88,51.78 36.86,51.81 36.86,52.12 36.61,52.12 36.61,51.81 36.6,51.78 36.56,51.76 36,51.76 36,51.41 35.99,51.37 35.95,51.35 32.93,51.35 32.83,51.46 32.83,52.07 33.38,52.62 40.93,52.62
DDR_VTT on BOTTOM (solid shape): 43.72,55.49 43.72,53.26 43.47,53.01 41.49,53.01 41.39,52.9 41.39,51.33 41.28,51.23 40.78,51.23 40.67,51.33 40.67,52.69 40.65,52.72 31.32,52.72 29.6,51 28.63,51 28.14,50.5 28.14,45.86 28.07,45.79 27.16,45.79 26.93,46.02 26.93,47.67 27.72,47.67 27.72,48.05 27.34,48.05 27.34,47.67 26.93,47.67 26.93,48.94 27.72,48.94 27.72,49.32 27.34,49.32 27.34,48.94 26.93,48.94 26.93,50.21 27.72,50.21 27.72,50.59 27.34,50.59 27.34,50.21 26.93,50.21 26.93,51.48 28.58,53.13 38.13,53.13 38.13,53.39 42.33,53.39 42.33,53.77 42.07,53.77 42.07,53.39 38.13,53.39 38.13,53.51 37.75,53.51 37.75,53.13 36.61,53.13 36.61,53.51 36.23,53.51 36.23,53.13 35.09,53.13 35.09,53.51 34.71,53.51 34.71,53.13 33.56,53.13 33.56,53.51 33.18,53.51 33.18,53.13 32.04,53.13 32.04,53.51 31.66,53.51 31.66,53.13 28.58,53.13 29.37,53.92 38.06,53.92 38.11,53.97 38.31,54.15 39.18,54.15 39.81,54.78 42.33,54.78 42.33,55.16 42.07,55.16 42.07,54.78 39.81,54.78 40.57,55.55 43.67,55.55
FE_3V3 on BOTTOM (solid shape): 51.6,45.36 52.08,45.36 52.37,45.07 52.37,44.23 52.59,44.01 52.59,43.63 52.51,43.56 52.05,43.56 51.95,43.66 51.95,44.57 51.82,44.7 51.19,44.7 50.96,44.47 50.96,43.89 50.94,43.86 50.4,43.86 50.33,43.94 50.33,45.54 50.48,45.69 51.27,45.69
HDMI_TX_1V1 on BOTTOM (solid shape): 61.58,43.63 61.58,43.1 61.53,43.05 61.38,43.05 61.02,42.69 61.02,41.98 61.12,41.88 61.45,41.88 61.53,41.8 61.53,41.12 61.4,40.99 60.82,40.99 60.61,40.79 60.61,40.23 60.56,40.18 59.85,40.18 59.85,40.56 60.49,40.56 60.49,40.81 60.23,40.81 60.23,40.56 59.85,40.56 59.85,40.69 59.88,40.71 59.88,41.32 59.88,41.37 59.88,41.42 59.88,41.45 59.88,41.63 59.77,41.73 59.59,41.73 59.57,41.73 59.52,41.74 59.48,41.73 59.45,41.73 59.22,41.73 59.19,41.75 59.19,42.04 60.67,42.04 60.67,42.42 60.29,42.42 60.29,42.04 59.19,42.04 59.19,42.57 59.22,42.59 60.28,42.59 61.04,43.35 61.04,43.63 61.07,43.66 61.55,43.66
HDMI_TX_3V3 on BOTTOM (solid shape): 59.01,45.36 59.01,44.88 59.17,44.72 60.54,44.72 60.56,44.7 60.56,43.74 60.53,43.72 60.51,43.67 60.48,43.64 60.39,43.58 60.32,43.57 60.26,43.58 60.2,43.6 60.15,43.64 60.11,43.68 60.08,43.72 60.08,44.14 60.03,44.19 58.91,44.19 58.71,44.39 58.71,44.77 58.48,45 57.87,45 57.84,45.03 57.84,45.51 57.87,45.54 58.84,45.54
Net_50 on BOTTOM (solid shape): outline of 286 points within 0.51,0.51 7.62,87.84
Net_51 on BOTTOM (solid shape): outline of 189 points within 99.14,0.51 106.25,87.84
Net_52 on POWER03 (solid shape): outline of 264 points within 0.51,0.51 7.62,87.84
Net_53 on POWER03 (solid shape): outline of 178 points within 99.14,0.51 106.25,87.84
Net_54 on GND02 (solid shape): outline of 265 points within 0.51,0.51 7.62,87.84
Net_55 on GND02 (solid shape): outline of 178 points within 99.14,0.51 106.25,87.84
Net_56 on TOP (solid shape): outline of 286 points within 0.51,0.51 7.62,87.84
Net_57 on TOP (solid shape): outline of 189 points within 99.14,0.51 106.25,87.84
Net_134 on BOTTOM (solid shape): 35.47,81 32.8,81 32.8,82.27 35.47,82.27
Net_135 on BOTTOM (solid shape): 23.91,81 21.24,81 21.24,82.27 23.91,82.27
Net_136 on BOTTOM (solid shape): 34.45,82.77 31.78,82.77 31.78,84.04 34.45,84.04
Net_137 on BOTTOM (solid shape): 22.89,82.77 20.23,82.77 20.23,84.04 22.89,84.04
USB01_1V1 on BOTTOM (solid shape): 57.54,41.63 57.68,41.63 57.68,41.62 58.08,41.62 58.15,41.55 58.15,41.25 58.07,41.17 57.51,41.17 57.41,41.07 57.41,39.34 57.39,39.31 56.85,39.31 56.83,39.34 56.83,39.8 57.31,39.8 57.31,40.43 57.06,40.43 57.06,39.8 56.83,39.8 56.83,41.07 57.31,41.07 57.31,41.32 57.06,41.32 57.06,41.07 56.83,41.07 56.83,41.78 56.85,41.8 57.36,41.8
USB01_3V3 on BOTTOM (solid shape): 55.14,45.73 55.14,44.97 55,44.83 55,42.77 54.97,42.74 54.44,42.74 54.36,42.82 54.36,43.23 54.9,43.23 54.9,43.48 54.64,43.48 54.64,43.23 54.36,43.23 54.36,44.12 54.9,44.12 54.9,44.37 54.64,44.37 54.64,44.12 54.36,44.12 54.36,44.7 54.21,44.85 54.21,45.64 54.34,45.77 55.1,45.77
VDAC_3V3 on BOTTOM (solid shape): 68.41,44.85 68.41,44.17 68.36,44.12 66.88,44.12 66.85,44.13 66.8,44.15 66.75,44.15 66.69,44.15 66.64,44.15 66.59,44.13 66.53,44.1 66.49,44.07 66.45,44.03 66.42,43.99 66.41,43.96 66.09,43.65 65.32,43.65 65.21,43.53 65.01,43.53 64.88,43.66 64.88,43.86 65.57,43.86 65.57,44.12 65.31,44.12 65.31,43.86 64.88,43.86 64.88,44.12 65.03,44.27 65.05,44.27 65.07,44.26 65.12,44.26 65.17,44.26 65.19,44.27 65.95,44.27 66.25,44.57 66.25,45.03 66.28,45.06 68.21,45.06
$4N777 on TOP (solid shape): 72.42,50.14 72.42,49.62 72.42,49.55 72.79,49.18 74.75,49.18 74.89,49.04 74.89,47.16 74.81,47.09 70.9,47.09 70.79,47.2 70.79,50.22 70.82,50.26 72.3,50.26
$4N814 on TOP (solid shape): 69.18,18.28 72.62,18.28 72.74,18.16 72.74,16.43 72.61,16.3 70.04,16.3 69.26,15.52 69.26,13.96 69.25,13.96 68.61,13.96 68.6,13.97 68.6,16.42 68.81,16.63 68.81,18.04 69.05,18.28 69.18,18.28
$4N882 on TOP (solid shape): 21.93,46.35 21.93,42.24 21.75,42.06 18.35,42.06 18.2,42.21 18.2,43.91 18.47,44.19 19.67,44.19 19.86,44.38 19.86,46.36 20.05,46.55 21.73,46.55
$4N983 on TOP (solid shape): 77.23,60.1 77.23,58.85 77.01,58.62 73.55,58.62 73.55,58.62 73.4,58.62 72.81,58.04 70.14,58.04 70.01,58.17 70.01,58.8 70.1,58.88 71.97,58.88 72.27,59.18 72.27,59.55 72.94,60.22 77.11,60.22
$10N1108 on BOTTOM (solid shape): 45.12,55.47 45.12,50.47 45.25,50.34 46.14,50.34 46.26,50.21 46.26,49.32 46.14,49.2 45.36,49.2 44.5,49.2 44.1,49.2 43.98,49.32 43.98,49.45 45.88,49.45 45.88,49.83 45.5,49.83 45.5,49.45 43.98,49.45 43.98,51.1 44.61,51.1 44.61,51.35 44.36,51.35 44.36,51.1 43.98,51.1 43.98,52.12 44.61,52.12 44.61,52.37 44.36,52.37 44.36,52.12 43.98,52.12 43.98,55.49 44.1,55.62 44.97,55.62
$14N488 on TOP (solid shape): 91.15,74.55 91.15,73.41 90.9,73.15 86.96,73.15 86.45,73.66 85.06,73.66 85.06,75.95 85.18,76.07 89.63,76.07
$14N488 on BOTTOM (solid shape): 93.77,72.44 93.77,62.84 88.56,57.63 85.13,57.63 84.7,58.06 84.7,59.36 85.03,59.69 87.06,59.69 91.38,64.01 91.38,71.4 89.38,73.41 89.38,74.68 89.63,74.93 91.28,74.93
$14N524 on TOP (solid shape): 79.92,8.56 81.44,8.56 81.7,8.3 81.7,6.78 81.44,6.52 79.54,6.52 78.39,5.38 76.49,5.38 76.36,5.51 76.36,9.95 76.49,10.08 78.39,10.08
$14N524 on BOTTOM (solid shape): 86.1,11.07 86.1,9.06 83.56,6.52 79.66,6.52 79.54,6.65 79.54,8.43 79.79,8.68 83.43,8.68 84.7,9.95 84.7,11.07 85.07,11.44 85.73,11.44
$15N771 on TOP (solid shape): 73.44,6.27 74.33,6.27 74.46,6.14 74.46,4.75 74.84,4.36 75.98,4.36 76.11,4.24 76.11,1.44 75.98,1.32 74.08,1.32 73.95,1.44 73.95,2.97 72.93,3.98 70.77,3.98 70.65,4.11 70.65,5.46 74.01,5.46 74.01,5.97 73.5,5.97 73.5,5.46 70.65,5.46 70.65,6.14 70.77,6.27 71.54,6.27 71.61,6.35 71.79,6.52 73.19,6.52
$15N777 on BOTTOM (solid shape): 19.27,62.2 19.27,56.82 19.14,56.69 18.12,56.69 17.93,56.88 17.93,58.8 19.02,58.8 19.02,59.18 18.64,59.18 18.64,58.8 17.93,58.8 17.93,59.94 17.93,59.95 17.74,60.14 17.74,62.15 17.94,62.35 19.11,62.35
$15N783 on BOTTOM (solid shape): 19.36,63.74 19.36,62.82 19.19,62.66 16.22,62.66 16.09,62.78 16.09,63.8 16.22,63.93 19.17,63.93
$17N177 on BOTTOM (solid shape): 33.79,72 33.79,70.42 33.66,70.29 24.72,70.29 24.62,70.39 24.62,71.06 24.72,71.16 31.83,71.16 31.99,71.31 31.99,72 32.17,72.17 33.61,72.17

Small or netless copper shapes (teardrops, artwork), in the pictures only: 3 on TOP

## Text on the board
BOTTOM: HI3798MDMO1D VER.E ARTWORK BOTTOM
Ref Des/Silkscreen Bottom: 0400 | 0350 | 1014 | 0295 | 0464 | 2013-05-29 | 2013-08-08 | 2013-09-26 | 2014-06-17 | 2014-07-14 | 2014-07-19 | 2014-08-12 | 2014-10-31 | 0113 | 0522 | 0483 | 0592 | UPDATE | VER.B | VER.C | VER.D | VER.A | VER.E | 01 | 113536 | 114626 | 115584 | 116241 | 120241 | 120783 | 120906 | 121252 | 122397 | A | HI3798MDMO1D VER.E SILKSCREEN BOTTOM
User.Comments: HI3798MDMO1D VER.E SOLDMASK TOP | HI3798MDMO1D VER.E SOLDMASK BOTTOM
TOP: HI3798MDMO1D VER.E ARTWORK TOP
Ref Des/Silkscreen Top: 113536 | 114626 | 115584 | 116241 | 120241 | 120783 | 120906 | 121252 | 122397 | 01 | VER.B | VER.C | VER.D | VER.A | VER.E | UPDATE | 0113 | 0522 | 0483 | 0592 | 0464 | 2013-05-29 | 2013-08-08 | 2013-09-26 | 2014-06-17 | 2014-07-14 | 2014-07-19 | 2014-08-12 | 2014-10-31 | 0400 | 0350 | 1014 | 0295 | HI3798MDMO1D VER.E | HI3798MDMO1D VER.E SILKSCREEN TOP
GND02: HI3798MDMO1D VER.E GROUND PLANE02
POWER03: HI3798MDMO1D VER.E POWER PLANE03
DIMENSION: 120241 | 120783 | 120906 | 121252 | 122397 | 113536 | 114626 | 115584 | 116241 | REV | 01 | VER.A | VER.B | VER.C | VER.D | VER.E | UPDATE | 0592 | 0464 | 0483 | 0113 | 0522 | 2014-06-17 | 2014-07-14 | 2014-07-19 | 2014-08-12 | 2014-10-31 | 2013-05-29 | 2013-08-08 | 2013-09-26 | 1014 | 0295 | 0400 | 0350 | HI3798MDMO1D_VER.E | Hi-Tg | 150 | C | Single Impedance | Diff Impedance | 100 ohm | 90 ohm | 50 ohm | PREPREG | GND02 | ART01 | ART04 | POWWE03 | CORE | Layer | 1,4 | Trace Width(mil) | Trace W/S(mil) | 4.5/6.0 | 6.0/7.0 | Layer Stack up | Solder Bot | Silk Bot | 5 | Solder Top | Silk Top | Tolerance | + | - | 10% | Frequency(MHZ) | Default | Thickness (mil) | 1.8(0.5oz+plating) | 4.0 | 1.2(1.0oz) | XXX | Remark | Notes3: | For this PN,Soldermask should be covered at all required location and | no red solder(copper color) is allowed at BGA area | 15 | HI3798MDMO1D VER.E DRILL CHART | 1--Gerber TOP | 2--GROUND PLANE02 | 3--POWER PLANE03 | 4--Gerber BOTTOM | 8XR2[78]
DISPLAY_BOTTOM: HI3798MDMO1D VER.E PASTEMASK BOTTOM
DISPLAY_TOP: HI3798MDMO1D VER.E PASTEMASK TOP
User.10: FIGURE | SIZE | 8.0 | 10.0 | 20.0 | 30.0 | 32.0 | 36.0 | 38.0 | 40.0 | 52.0 | 90.0 | 95.0 | 142.0 | 43.0 | 80.0 | 135.0 | 52.0x24.0 | 60.0x32.0 | 82.0x36.0 | 96.0x26.0 | 96.0x30.0 | 105.0x36.0 | 116.0x30.0 | DRILL CHART: TOP to BOTTOM | ALL UNITS ARE IN MILS | PLATED | NON-PLATED | QTY | 547 | 835 | 4 | 9 | 3 | 13 | 18 | 2 | 32 | 5 | 1
